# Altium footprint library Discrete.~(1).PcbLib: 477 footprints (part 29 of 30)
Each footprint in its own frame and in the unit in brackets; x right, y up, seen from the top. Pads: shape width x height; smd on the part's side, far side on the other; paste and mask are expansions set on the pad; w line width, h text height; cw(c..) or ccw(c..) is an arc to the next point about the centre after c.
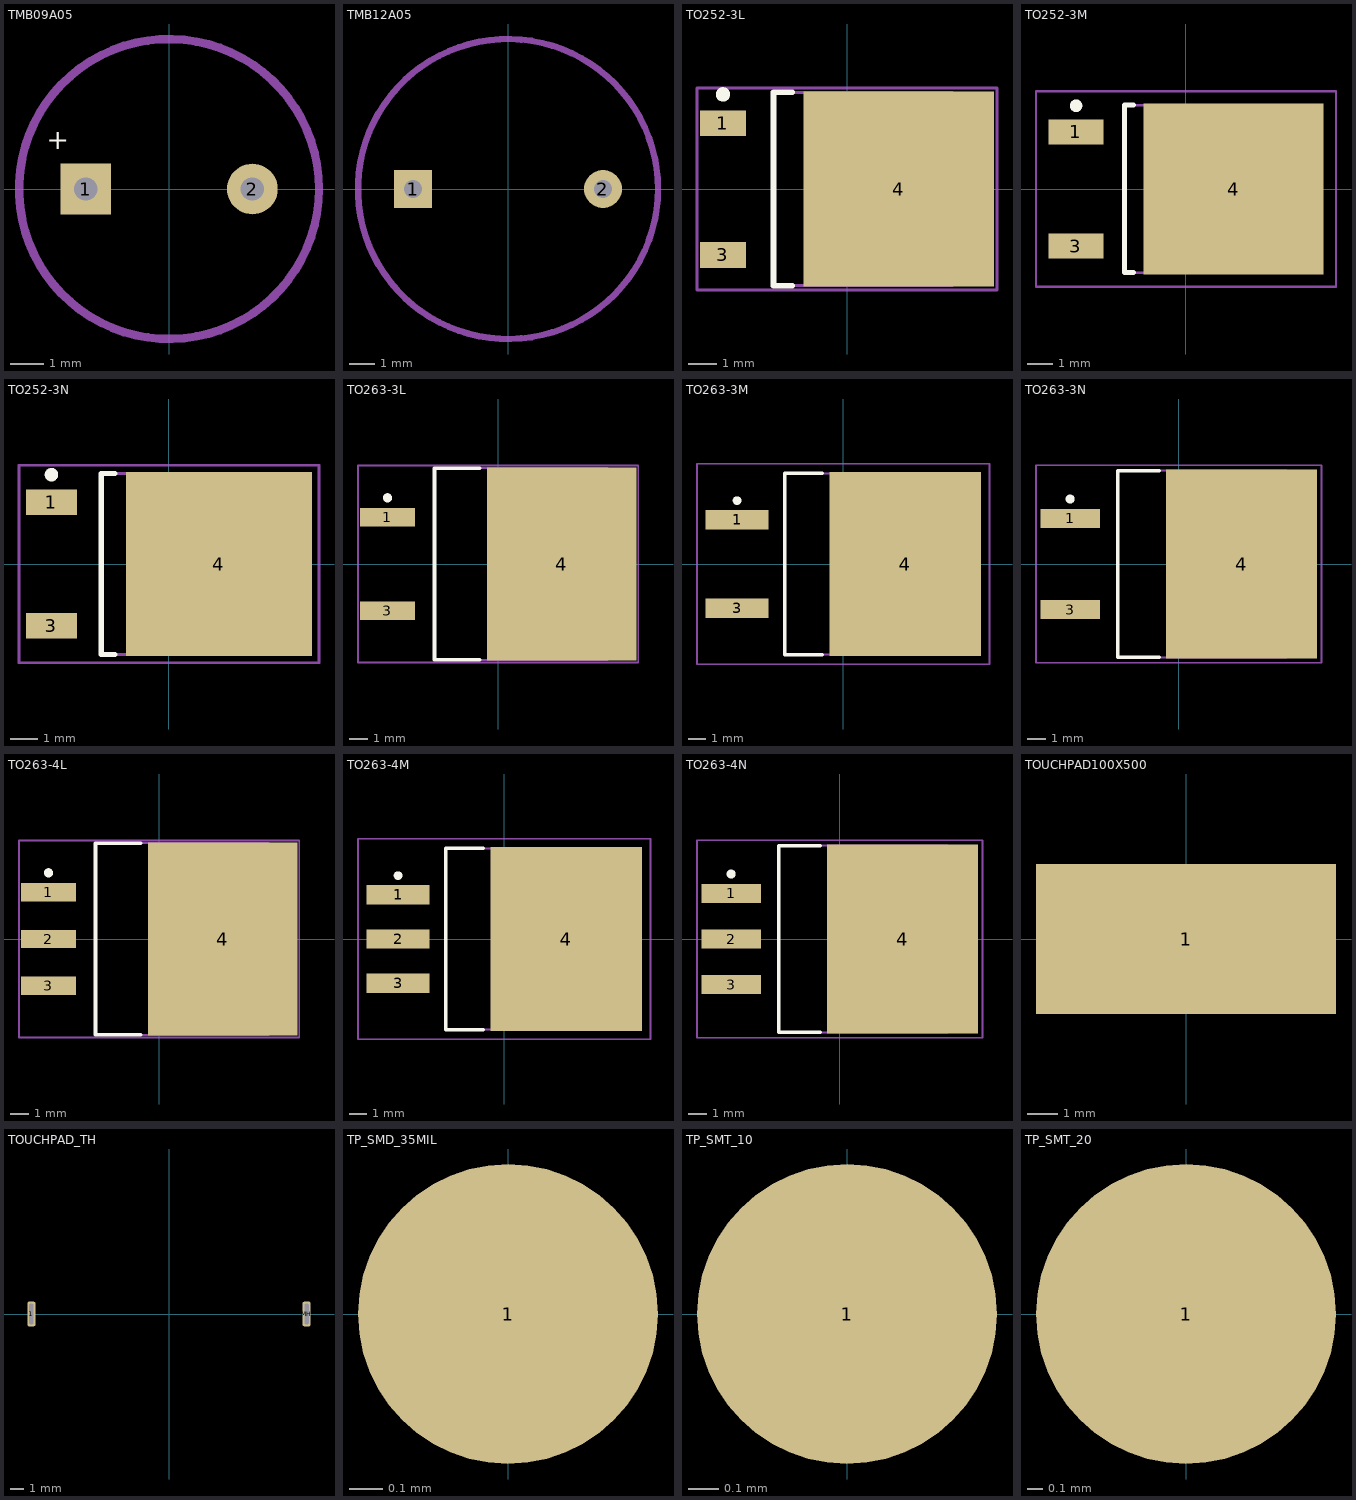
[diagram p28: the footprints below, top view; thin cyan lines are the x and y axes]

## TMB09A05 [mm] "3V, 9mm, Buzzer"
pads (2):
  rect 1.524x1.524 hole 0.7: 1(-2.5,0)
  round 1.524 hole 0.7: 2(2.5,0)
Top Overlay:
  text "+" at -3,1 h1.02
Mechanical 13:
  circle w0.254: c0,0 r4.5
3D body: height 5.55, standoff 0, extent -0.992,-0.998 1,0.998
3D body: height 5.5, standoff 0, extent -4.5,-4.5 4.5,4.5

## TMB12A05 [mm] "5V, 12mm, Buzzer"
pads (2):
  rect 1.524x1.524 hole 0.7: 1(-3.8,0)
  round 1.524 hole 0.7: 2(3.8,0)
Mechanical 13:
  circle w0.254: c0,0 r6
3D body "cem-1205c.stp": height 9.5, standoff -4.5, extent -6,-6 6,6

## TO252-3L [mm] "D-PAK, 4-Leads, Body 6.1x6.5mm, Pitch 2.28mm, Lead Span 9.7mm, IPC High Density"
height 2.38
pads (3):
  rect 1.6x0.9 smd: 1(-4.3,2.28) 3(-4.3,-2.28)
  rect 6.6x6.75 smd: 4(1.8,0)
Top Overlay:
  circle w0.25: c-4.3,3.28 r0.125
  lines w0.2: -1.9,-3.35 -2.55,-3.35 -2.55,3.35 -1.9,3.35
Mechanical 13:
  lines w0.1: -2.55,-3.35 -2.55,3.35 3.65,3.35 3.65,-3.35 -2.55,-3.35
Mechanical 15:
  lines w0.1: -0.5,0 0.5,0 ; 0,-0.5 0,0.5 ; -5.2,-3.5 -5.2,3.5 5.2,3.5 5.2,-3.5 -5.2,-3.5
3D body "TO252.STEP": height 2.3, standoff -0.01, extent -4.532,-3.25 4.887,3.25

## TO252-3M [mm] "D-PAK, 4-Leads, Body 6.1x6.5mm, Pitch 2.28mm, Lead Span 9.7mm, IPC Low Density"
height 2.38
pads (3):
  rect 2.2x1 smd: 1(-4.4,2.28) 3(-4.4,-2.28)
  rect 7.2x6.85 smd: 4(1.9,0)
Top Overlay:
  circle w0.25: c-4.4,3.33 r0.125
  lines w0.2: -2.1,-3.35 -2.45,-3.35 -2.45,3.35 -2.1,3.35
Mechanical 13:
  lines w0.1: -2.45,-3.35 -2.45,3.35 3.75,3.35 3.75,-3.35 -2.45,-3.35
Mechanical 15:
  lines w0.1: -0.5,0 0.5,0 ; 0,-0.5 0,0.5 ; -6,-3.9 -6,3.9 6,3.9 6,-3.9 -6,-3.9
3D body "TO252.STEP": height 2.3, standoff -0.01, extent -4.532,-3.25 4.887,3.25

## TO252-3N [mm] "D-PAK, 4-Leads, Body 6.1x6.5mm, Pitch 2.28mm, Lead Span 9.7mm, IPC Medium Density"
height 2.38
pads (3):
  rect 1.9x0.95 smd: 1(-4.35,2.28) 3(-4.35,-2.28)
  rect 6.9x6.8 smd: 4(1.85,0)
Top Overlay:
  circle w0.25: c-4.35,3.305 r0.125
  lines w0.2: -2,-3.35 -2.5,-3.35 -2.5,3.35 -2,3.35
Mechanical 13:
  lines w0.1: -2.5,-3.35 -2.5,3.35 3.7,3.35 3.7,-3.35 -2.5,-3.35
Mechanical 15:
  lines w0.1: -0.5,0 0.5,0 ; 0,-0.5 0,0.5 ; -5.55,-3.65 -5.55,3.65 5.55,3.65 5.55,-3.65 -5.55,-3.65
3D body "TO252.STEP": height 2.3, standoff -0.01, extent -4.532,-3.25 4.887,3.25

## TO263-3L [mm] "D2-PAK, 4-Leads, Body 9.4x10.2mm, Pitch 2.54mm, Lead Span 14.3mm, IPC High Density"
height 4.65
pads (3):
  rect 3x1 smd: 1(-6,2.54) 3(-6,-2.54)
  rect 8.1x10.45 smd: 4(3.45,0)
Top Overlay:
  circle w0.25: c-6,3.59 r0.125
  lines w0.2: -1,-5.2 -3.45,-5.2 -3.45,5.2 -1,5.2
Mechanical 13:
  lines w0.1: -3.45,-5.2 5.95,-5.2 5.95,5.2 -3.45,5.2 -3.45,-5.2
Mechanical 15:
  lines w0.1: -0.5,0 0.5,0 ; 0,-0.5 0,0.5 ; -7.6,-5.35 7.6,-5.35 7.6,5.35 -7.6,5.35 -7.6,-5.35
3D body: height 4.65, standoff 0, extent -3.45,-5.2 5.95,5.2

## TO263-3M [mm] "D2-PAK, 4-Leads, Body 9.4x10.2mm, Pitch 2.54mm, Lead Span 14.3mm, IPC Low Density"
height 4.65
pads (3):
  rect 3.6x1.1 smd: 1(-6.1,2.54) 3(-6.1,-2.54)
  rect 8.7x10.55 smd: 4(3.55,0)
Top Overlay:
  circle w0.25: c-6.1,3.64 r0.125
  lines w0.2: -1.2,-5.2 -3.35,-5.2 -3.35,5.2 -1.2,5.2
Mechanical 13:
  lines w0.1: -3.35,-5.2 -3.35,5.2 6.05,5.2 6.05,-5.2 -3.35,-5.2
Mechanical 15:
  lines w0.1: -0.5,0 0.5,0 ; 0,-0.5 0,0.5 ; -8.4,-5.75 -8.4,5.75 8.4,5.75 8.4,-5.75 -8.4,-5.75
3D body: height 4.65, standoff 0, extent -3.35,-5.2 6.05,5.2

## TO263-3N [mm] "D2-PAK, 4-Leads, Body 9.4x10.2mm, Pitch 2.54mm, Lead Span 14.3mm, IPC Medium Density"
height 4.65
pads (3):
  rect 3.3x1.05 smd: 1(-6.05,2.54) 3(-6.05,-2.54)
  rect 8.4x10.5 smd: 4(3.5,0)
Top Overlay:
  circle w0.25: c-6.05,3.615 r0.125
  lines w0.2: -1.1,-5.2 -3.4,-5.2 -3.4,5.2 -1.1,5.2
Mechanical 13:
  lines w0.1: -3.4,-5.2 6,-5.2 6,5.2 -3.4,5.2 -3.4,-5.2
Mechanical 15:
  lines w0.1: -0.5,0 0.5,0 ; 0,-0.5 0,0.5 ; -7.95,-5.5 7.95,-5.5 7.95,5.5 -7.95,5.5 -7.95,-5.5
3D body: height 4.65, standoff 0, extent -3.4,-5.2 6,5.2

## TO263-4L [mm] "D2-PAK, 4-Leads, Body 9.4x10.2mm, Pitch 2.54mm, Lead Span 14.3mm, IPC High Density"
height 4.65
pads (4):
  rect 3x1 smd: 1(-6,2.54) 2(-6,0) 3(-6,-2.54)
  rect 8.1x10.45 smd: 4(3.45,0)
Top Overlay:
  circle w0.25: c-6,3.59 r0.125
  lines w0.2: -1,-5.2 -3.45,-5.2 -3.45,5.2 -1,5.2
Mechanical 13:
  lines w0.1: -3.45,-5.2 -3.45,5.2 5.95,5.2 5.95,-5.2 -3.45,-5.2
Mechanical 15:
  lines w0.1: -0.5,0 0.5,0 ; 0,-0.5 0,0.5 ; -7.6,-5.35 -7.6,5.35 7.6,5.35 7.6,-5.35 -7.6,-5.35
3D body: height 4.65, standoff 0, extent -3.45,-5.2 5.95,5.2

## TO263-4M [mm] "D2-PAK, 4-Leads, Body 9.4x10.2mm, Pitch 2.54mm, Lead Span 14.3mm, IPC Low Density"
height 4.65
pads (4):
  rect 3.6x1.1 smd: 1(-6.1,2.54) 2(-6.1,0) 3(-6.1,-2.54)
  rect 8.7x10.55 smd: 4(3.55,0)
Top Overlay:
  circle w0.25: c-6.1,3.64 r0.125
  lines w0.2: -1.2,-5.2 -3.35,-5.2 -3.35,5.2 -1.2,5.2
Mechanical 13:
  lines w0.1: -3.35,-5.2 -3.35,5.2 6.05,5.2 6.05,-5.2 -3.35,-5.2
Mechanical 15:
  lines w0.1: -0.5,0 0.5,0 ; 0,-0.5 0,0.5 ; -8.4,-5.75 -8.4,5.75 8.4,5.75 8.4,-5.75 -8.4,-5.75
3D body: height 4.65, standoff 0, extent -3.35,-5.2 6.05,5.2

## TO263-4N [mm] "D2-PAK, 4-Leads, Body 9.4x10.2mm, Pitch 2.54mm, Lead Span 14.3mm, IPC Medium Density"
height 4.65
pads (4):
  rect 3.3x1.05 smd: 1(-6.05,2.54) 2(-6.05,0) 3(-6.05,-2.54)
  rect 8.4x10.5 smd: 4(3.5,0)
Top Overlay:
  circle w0.25: c-6.05,3.615 r0.125
  lines w0.2: -1.1,-5.2 -3.4,-5.2 -3.4,5.2 -1.1,5.2
Mechanical 13:
  lines w0.1: -3.4,-5.2 6,-5.2 6,5.2 -3.4,5.2 -3.4,-5.2
Mechanical 15:
  lines w0.1: -0.5,0 0.5,0 ; 0,-0.5 0,0.5 ; -7.95,-5.5 7.95,-5.5 7.95,5.5 -7.95,5.5 -7.95,-5.5
3D body: height 4.65, standoff 0, extent -3.4,-5.2 6,5.2

## TOUCHPAD100X500 [mm]
pads (1):
  rect 10x5 smd: 1(0,0)

## TOUCHPAD_TH [mm]
pads (2):
  rrect50% 0.6x1.8 hole 0.3 slot 1.5 at 90 deg: 1(-10,0) MH(10,0)
3D body: height 2.5, standoff 2.2, extent -10.16,-4 10.135,4
3D body: height 2.2, standoff 0, extent 9.85,-4 10.15,4
3D body: height 2.2, standoff 0, extent -10.15,-4 -9.85,4

## TP_SMD_35MIL [mil]
pads (1):
  round 35 smd: 1(0,0)

## TP_SMT_10 [mm]
pads (1):
  round 1 smd: 1(0,0)

## TP_SMT_20 [mm]
pads (1):
  round 2 smd: 1(0,0)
